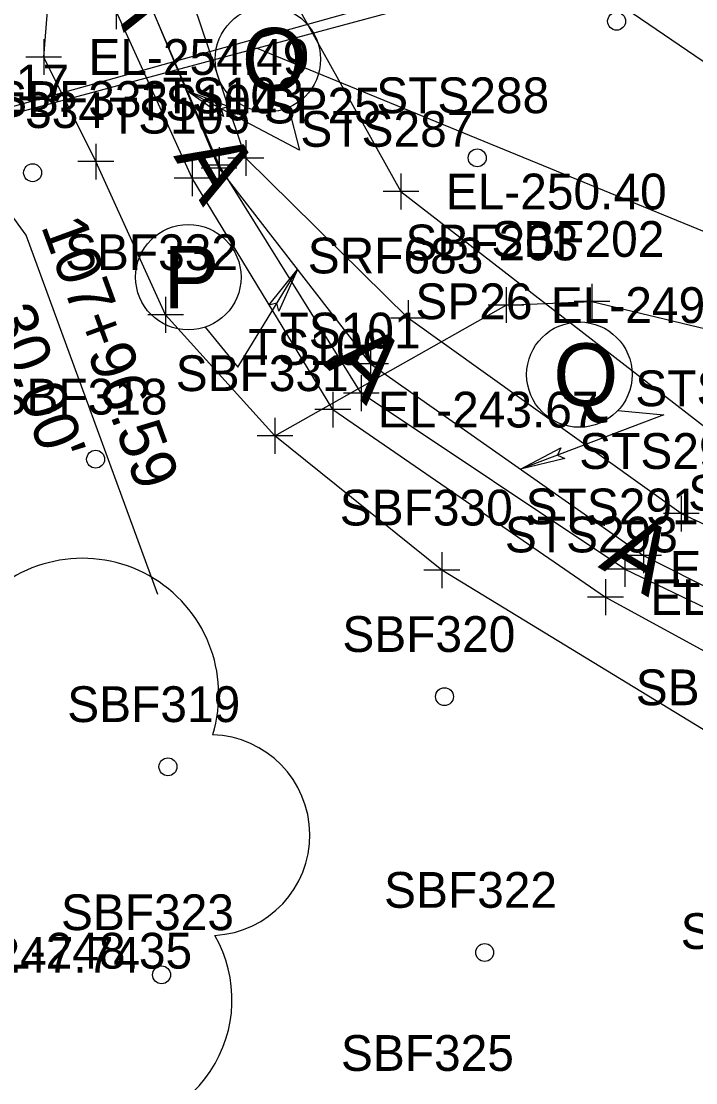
# Model space of a CAD drawing. Extents: x 818717 to 846077, y 440014 to 541392.
# Drawn here: x 831746.3 to 831821.7, y 492977.1 to 493095.8 of the extents above; entities that cross this region are included whole.
import ezdxf

# ---------------------------------------------------------------- set-up
doc = ezdxf.new("R2010")
doc.units = 0
for name, color, linetype in [('SURVEY - DRAINAGE - Bridge Hydraulic Data - Points - Elevations', 7, 'Continuous'), ('SURVEY - DRAINAGE - Bridge Hydraulic Data - Points - Locators', 7, 'Continuous'), ('SURVEY - DRAINAGE - Bridge Hydraulic Data - Points - Numbers', 7, 'Continuous'), ('SURVEY - DRAINAGE - Bridge Hydraulic Data with Text', 7, 'Continuous'), ('SURVEY - DRAINAGE - Natural Features', 7, 'Continuous'), ('SURVEY - DRAINAGE - Natural Features - Points - Elevations', 7, 'Continuous'), ('SURVEY - DRAINAGE - Natural Features - Points - Locators', 7, 'Continuous'), ('SURVEY - DRAINAGE - Natural Features - Points - Numbers', 7, 'Continuous'), ('SURVEY - DTM - Breaklines - Points - Elevations', 7, 'Continuous'), ('SURVEY - DTM - Spot Points - Locators', 7, 'Continuous'), ('SURVEY - DTM - Spot Points - Point Numbers', 7, 'Continuous'), ('SURVEY - PROPERTY - ROW Lines', 7, 'Continuous'), ('SURVEY - PROPERTY - ROW Lines Text', 7, 'Continuous'), ('SURVEY - PROPERTY - Station and Offset Flags', 7, 'Continuous'), ('SURVEY - UTILITIES - Electric (Overhead) with Text', 7, 'Continuous'), ('SURVEY - VEGETATION - Features - Points - Elevations', 7, 'Continuous'), ('SURVEY - VEGETATION - Features - Points - Locators', 7, 'Continuous'), ('SURVEY - VEGETATION - Features - Points - Numbers', 7, 'Continuous'), ('SURVEY - VEGETATION - Features with Text', 7, 'Continuous')]:
    doc.layers.add(name, color=color, linetype=linetype)

msp = doc.modelspace()

# ---------------------------------------------------------------- linework, layer by layer
at = {"layer": 'SURVEY - DRAINAGE - Bridge Hydraulic Data - Points - Locators'}
for p, q in [((831756.92, 493098.93), (831756.92, 493094.93)), ((831748.84, 493093.81), (831748.84, 493089.81)), ((831750.84, 493091.81), (831746.84, 493091.81)), ((831771.42, 493082.51), (831771.42, 493078.51)), ((831754.66, 493082.11), (831754.66, 493078.11)), ((831756.66, 493080.11), (831752.66, 493080.11)), ((831765.42, 493080.25), (831765.42, 493076.25)), ((831773.42, 493080.51), (831769.42, 493080.51)), ((831788.76, 493078.77), (831788.76, 493074.77)), ((831767.42, 493078.25), (831763.42, 493078.25)), ((831790.76, 493076.77), (831786.76, 493076.77)), ((831762.46, 493064.98), (831762.46, 493060.98)), ((831789.58, 493064.61), (831789.58, 493060.61)), ((831764.46, 493062.98), (831760.46, 493062.98)), ((831791.58, 493062.61), (831787.58, 493062.61)), ((831781.15, 493054.38), (831781.15, 493050.38)), ((831783.15, 493052.38), (831779.15, 493052.38)), ((831774.68, 493051.45), (831774.68, 493047.45)), ((831776.68, 493049.45), (831772.68, 493049.45)), ((831820.08, 493042.75), (831820.08, 493038.75)), ((831822.08, 493040.75), (831818.08, 493040.75)), ((831793.33, 493036.42), (831793.33, 493032.42)), ((831795.33, 493034.42), (831791.33, 493034.42)), ((831811.61, 493033.41), (831811.61, 493029.41)), ((831813.61, 493031.41), (831809.61, 493031.41))]:
    msp.add_line(p, q, dxfattribs=at)
at = {"layer": 'SURVEY - DRAINAGE - Bridge Hydraulic Data with Text'}
for p, q in [((831760.43, 493098.44), (831768.42, 493079.38)), ((831768.42, 493081.38), (831768.42, 493077.38)), ((831770.42, 493079.38), (831766.42, 493079.38)), ((831768.42, 493079.38), (831785.37, 493057.49)), ((831785.37, 493059.49), (831785.37, 493055.49)), ((831787.37, 493057.49), (831783.37, 493057.49)), ((831785.37, 493057.49), (831815.85, 493036.08)), ((831815.85, 493038.08), (831815.85, 493034.08)), ((831817.85, 493036.08), (831813.85, 493036.08)), ((831815.85, 493036.08), (831864.32, 493011.61))]:
    msp.add_line(p, q, dxfattribs=at)
for points in [[(831820.08, 493040.75), (831789.58, 493062.61), (831771.42, 493080.51), (831764.84, 493100.04), (831762.4, 493102.75), (831755.8, 493134.73), (831748.63, 493148.06), (831760.78, 493156.19)], [(831781.15, 493052.38), (831765.42, 493078.25), (831756.92, 493096.93), (831753.18, 493100.41), (831747.98, 493132.46), (831745, 493144.97)], [(831867.33, 492993.22), (831826.24, 493014.32), (831793.33, 493034.42), (831774.68, 493049.45), (831762.46, 493062.98), (831754.66, 493080.11), (831748.84, 493091.81), (831749.66, 493102.15)], [(831776.59, 493098.59), (831788.76, 493076.77), (831826.19, 493047.76), (831875.74, 493024.78), (831924.3, 492996.44), (831966.46, 492979.94), (832013.94, 492956.89), (832082.97, 492925.81)], [(831776.21, 493086.15), (831777.42, 493081.38), (831764.78, 493088.08)], [(831764.78, 493088.08), (831769.54, 493086.29), (831768.66, 493086.02), (831768.94, 493085.14), (831764.78, 493088.08)], [(831766.88, 493061.6), (831770.52, 493057.12), (831777.2, 493068.04)], [(831777.2, 493068.04), (831775.12, 493063.39), (831774.9, 493064.29), (831774.01, 493064.07), (831777.2, 493068.04)], [(831781.15, 493052.38), (831811.61, 493031.41), (831858.51, 493005.8), (831912.34, 492980.87), (831952.65, 492961.6), (832007.58, 492938.23), (832080.74, 492904.24)], [(831813, 493052.27), (831818.14, 493051.8), (831802.12, 493045.72)], [(831802.12, 493045.72), (831806.61, 493048.12), (831806.24, 493047.28), (831807.08, 493046.91), (831802.12, 493045.72)], [(831820.08, 493040.75), (831870.13, 493017.41), (831920.58, 492990.86), (831960.39, 492972.47), (832010.46, 492948.15), (832081.85, 492918.58)]]:
    msp.add_lwpolyline(points, dxfattribs=at)
for points in [[(831764.78, 493088.08), (831769.54, 493086.29), (831768.66, 493086.02), (831768.94, 493085.14)], [(831777.2, 493068.04), (831775.12, 493063.39), (831774.9, 493064.29), (831774.01, 493064.07)], [(831802.12, 493045.72), (831806.61, 493048.12), (831806.24, 493047.28), (831807.08, 493046.91)]]:
    msp.add_lwpolyline(points, close=True, dxfattribs=at)
for centre in [(831773.88, 493091.56), (831765, 493067.19), (831808.69, 493056.29)]:
    msp.add_circle(centre, 5.89, dxfattribs=at)
at = {"layer": 'SURVEY - DRAINAGE - Natural Features'}
for points in [[(831813.77, 493034.55), (831784.32, 493054.22), (831768.46, 493079.72), (831760.43, 493098.44), (831758.63, 493101.92), (831750.87, 493132.82), (831746.77, 493147.79), (831759.33, 493159.76), (831758.4, 493191.52), (831757.46, 493213.42), (831743.06, 493229.8), (831735.85, 493240.7)], [(831813.77, 493034.55), (831863.42, 493010.71), (831915.61, 492983.93), (831954.59, 492966.37), (832009.52, 492943.03), (832081.35, 492912.12)]]:
    msp.add_lwpolyline(points, dxfattribs=at)
at = {"layer": 'SURVEY - DRAINAGE - Natural Features - Points - Locators'}
for p, q in [((831768.46, 493081.72), (831768.46, 493077.72)), ((831770.46, 493079.72), (831766.46, 493079.72)), ((831784.32, 493056.22), (831784.32, 493052.22)), ((831786.32, 493054.22), (831782.32, 493054.22)), ((831813.77, 493036.55), (831813.77, 493032.55)), ((831815.77, 493034.55), (831811.77, 493034.55))]:
    msp.add_line(p, q, dxfattribs=at)
at = {"layer": 'SURVEY - DTM - Spot Points - Locators'}
for centre in [(831812.85, 493095.81), (831797.28, 493080.53), (831747.6, 493078.87), (831754.64, 493046.83), (831793.62, 493020.28), (831762.72, 493012.44), (831798.11, 492991.67), (831762.01, 492989.17)]:
    msp.add_circle(centre, 1, dxfattribs=at)
at = {"layer": 'SURVEY - PROPERTY - ROW Lines'}
msp.add_line((831738.36, 493083.6), (831806.89, 493102.02), dxfattribs=at)
at = {"layer": 'SURVEY - PROPERTY - ROW Lines Text'}
msp.add_lwpolyline([(831862.18, 493056.06), (831772.62, 493092.81)], dxfattribs=at)
at = {"layer": 'SURVEY - PROPERTY - Station and Offset Flags'}
msp.add_line((831761.59, 493031.7), (831746.89, 493071.87), dxfattribs=at)
for points in [[(831849.39, 493073.02), (831806.89, 493102.02)], [(831746.89, 493071.87), (831738.36, 493083.6)]]:
    msp.add_lwpolyline(points, dxfattribs=at)
at = {"layer": 'SURVEY - UTILITIES - Electric (Overhead) with Text'}
msp.add_lwpolyline([(832667.18, 493331.74), (832415.28, 493266.23), (832147.85, 493195.27), (831907.96, 493131.64), (831666.03, 493064.14), (831375.19, 492986.65), (831101.3, 492913.04)], dxfattribs=at)
at = {"layer": 'SURVEY - VEGETATION - Features - Points - Locators'}
for p, q in [((831800.5, 493066.07), (831800.5, 493062.07)), ((831810.1, 493066.46), (831810.1, 493062.46)), ((831802.5, 493064.07), (831798.5, 493064.07)), ((831812.1, 493064.46), (831808.1, 493064.46))]:
    msp.add_line(p, q, dxfattribs=at)
at = {"layer": 'SURVEY - VEGETATION - Features with Text'}
msp.add_lwpolyline([(831867.33, 492993.22), (831826.24, 493014.32), (831793.33, 493034.42), (831774.68, 493049.45), (831800.5, 493064.07), (831810.1, 493064.46), (831834.64, 493058.58), (831878.88, 493035.26), (831927.25, 493009.46), (831941.69, 493002.76)], dxfattribs=at)
for centre, radius, start, end in [((831753.17, 493020.52), 15.23, 342.8641, 138.7026), ((831767.35, 493004.8), 11.23, 273.117, 88.1173), ((831755.4, 492986.39), 14.48, 262.9581, 29.8037)]:
    msp.add_arc(centre, radius, start, end, dxfattribs=at)

# ---------------------------------------------------------------- texts
at = {"layer": 'SURVEY - DRAINAGE - Bridge Hydraulic Data - Points - Elevations'}
for s, p in [('EL-254.49', (831753.84, 493089.81)), ('EL-250.40', (831793.76, 493074.77)), ('EL-243.67', (831786.15, 493050.38)), ('EL-244.53', (831816.61, 493029.41))]:
    msp.add_text(s, height=4, dxfattribs=at).set_placement(p)
at = {"layer": 'SURVEY - DRAINAGE - Bridge Hydraulic Data - Points - Numbers'}
for s, p in [('TS103', (831762.14, 493085.51)), ('SBF333', (831743.42, 493085.11)), ('SP25', (831773.42, 493084.38)), ('TS105', (831756.13, 493083.25)), ('STS287', (831777.52, 493081.77)), ('SBF332', (831751.22, 493067.98)), ('SRF683', (831778.34, 493067.61)), ('SP26', (831790.37, 493062.49)), ('TS100', (831771.69, 493057.38)), ('SBF331', (831763.59, 493054.45)), ('STS289', (831814.94, 493052.76)), ('STS290', (831808.67, 493045.75)), ('SP27', (831820.85, 493041.08)), ('SBF330', (831781.92, 493039.42)), ('STS293', (831800.37, 493036.41)), ('SBF329', (831814.99, 493019.32)), ('SP7', (831820.01, 492992.06))]:
    msp.add_text(s, height=4, dxfattribs=at).set_placement(p)
at = {"layer": 'SURVEY - DRAINAGE - Bridge Hydraulic Data with Text'}
for rotation, p in [(288.1986, (831755.7, 493100.83)), (300.2411, (831763.29, 493080.73)), (316.3309, (831780.07, 493057.37)), (329.0614, (831810.7, 493034.79))]:
    msp.add_text('A', height=7.5, rotation=rotation, dxfattribs=at).set_placement(p)
for s, p in [('O', (831770.98, 493088.06)), ('P', (831762.22, 493063.69)), ('Q', (831805.77, 493052.79))]:
    msp.add_text(s, height=7, dxfattribs=at).set_placement(p)
at = {"layer": 'SURVEY - DRAINAGE - Natural Features - Points - Elevations'}
msp.add_text('EL-243.56', height=4, dxfattribs=at).set_placement((831818.77, 493032.55))
at = {"layer": 'SURVEY - DRAINAGE - Natural Features - Points - Numbers'}
for s, p in [('TS104', (831759.17, 493084.72)), ('TS101', (831775.19, 493059.22)), ('STS291', (831802.69, 493039.55))]:
    msp.add_text(s, height=4, dxfattribs=at).set_placement(p)
at = {"layer": 'SURVEY - DTM - Breaklines - Points - Elevations'}
for s, p in [('EL-247.74', (831734.91, 492989.41)), ('EL-248.35', (831740.74, 492989.87))]:
    msp.add_text(s, height=4, dxfattribs=at).set_placement(p)
at = {"layer": 'SURVEY - DTM - Spot Points - Point Numbers'}
for s, p in [('SBF317', (831732.35, 493086.96)), ('STS288', (831785.99, 493085.53)), ('SBF334', (831736.36, 493083.87)), ('SBF318', (831743.35, 493051.83)), ('SBF320', (831782.21, 493025.28)), ('SBF319', (831751.47, 493017.44)), ('SBF322', (831786.87, 492996.67)), ('SBF323', (831750.77, 492994.17)), ('SBF325', (831782.05, 492978.43))]:
    msp.add_text(s, height=4, dxfattribs=at).set_placement(p)
at = {"layer": 'SURVEY - PROPERTY - Station and Offset Flags'}
for s, p in [('107+96.59', (831748.5, 493072.92)), ("30.00'", (831742.78, 493063.1))]:
    msp.add_text(s, height=5, rotation=290.101, dxfattribs=at).set_placement(p)
at = {"layer": 'SURVEY - VEGETATION - Features - Points - Elevations'}
msp.add_text('EL-249.94', height=4, dxfattribs=at).set_placement((831805.5, 493062.07))
at = {"layer": 'SURVEY - VEGETATION - Features - Points - Numbers'}
for s, p in [('SBF203', (831789.26, 493069.07)), ('SBF202', (831798.86, 493069.46))]:
    msp.add_text(s, height=4, dxfattribs=at).set_placement(p)

doc.saveas('drawing.dxf')
